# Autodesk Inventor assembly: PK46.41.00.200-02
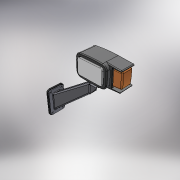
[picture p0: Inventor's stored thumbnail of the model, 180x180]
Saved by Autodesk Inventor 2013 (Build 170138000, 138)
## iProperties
Created: 2005-07
Part Number: PK46.41.00.200-02
Document SubType Name: Assembly
Designer: tedescj
Manufacturer: Standard
Standards Organization: Custom
Author: PVitaliy
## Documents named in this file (8)
- C:\Product Design Suite 2013 Test Drive\Dynamic Simulation\Workspace\Assy, Chassis, Front\PK46.41.00.200-02.iam
- C:\Product Design Suite 2013 Test Drive\Dynamic Simulation\Workspace\Assy, Chassis, Front\05.483.000-02.ipt
- C:\Product Design Suite 2013 Test Drive\Dynamic Simulation\Workspace\Assy, Chassis, Front\D395A-0401269-01.ipt
- C:\Product Design Suite 2013 Test Drive\Dynamic Simulation\Workspace\Assy, Chassis, Front\PK46.41.00.210-02.iam
- C:\Product Design Suite 2013 Test Drive\Dynamic Simulation\Workspace\Assy, Chassis, Front\10.65G.019.ipt
- C:\Product Design Suite 2013 Test Drive\Dynamic Simulation\Workspace\Assy, Chassis, Front\M10-6H.5.019(S16).ipt
- C:\Product Design Suite 2013 Test Drive\Dynamic Simulation\Workspace\Assy, Chassis, Front\D395A-0401270.ipt
- C:\Product Design Suite 2013 Test Drive\Dynamic Simulation\Workspace\Assy, Chassis, Front\PK46.21.01.093.ipt
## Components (7 placed, 7 different names)
1. 05.483.000-02:1 — Вставка:1
2. D395A-0401269-01:1 — Вставка:6
3. PK46.41.00.210-02:1 [sub-assembly] — Вставка:6, Вставка:1, Insert:9, Insert:11, Insert:8, Insert:7
4. 10.65G.019:1 — Insert:9, Insert:10
5. M10-6H.5.019(S16):1 — Insert:10
6. D395A-0401270:1 — Insert:11
7. PK46.21.01.093:1 — Insert:8, Insert:7
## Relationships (7: Insert 7)
- Вставка:6 [Insert]: D395A-0401269-01:1 ↔ PK46.41.00.210-02:1
- Вставка:1 [Insert]: 05.483.000-02:1 ↔ PK46.41.00.210-02:1
- Insert:9: PK46.41.00.210-02:1 ↔ 10.65G.019:1
- Insert:10: 10.65G.019:1 ↔ M10-6H.5.019(S16):1
- Insert:11: PK46.41.00.210-02:1 ↔ D395A-0401270:1
- Insert:8: PK46.41.00.210-02:1 ↔ PK46.21.01.093:1
- Insert:7: PK46.41.00.210-02:1 ↔ PK46.21.01.093:1
